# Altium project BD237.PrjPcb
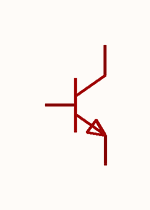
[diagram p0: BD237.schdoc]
1 sheet, 1 parts. Net scope: global (net labels, ports and power ports of the same name join across sheets).

## Sheet BD237.schdoc
size 127 x 101 mm

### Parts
Q?  bd237_c45991  [TO-126-3_L7.6-W2.7-P2.30-L]  (value not drawn)

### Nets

Not connected (* = marked no-connect by the designer): Q? 1(E) 2(C) 3(B)

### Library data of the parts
Q? = bd237_c45991: 晶体管类型:NPN;集电极电流(Ic):2A;集射极击穿电压(Vceo):80V;耗散功率(Pd):25W;直流电流增益(hFE):25;; Manufacturer: CJ(江苏长电/长晶); Symbol: BD237; AddInBom: yes; ModelId: 7e16fa0fc5b945c899301d14551435f6; ModelTransform: 299.212,106.6927,0,0,0,0,0,7.992,-196.85; type: NPN; Current - Collector(Ic): 2A; Collector - Emitter Voltage VCEO: 80V; Pd - Power Dissipation: 25W; DC Current Gain: 25; Transition frequency(fT): 3MHz; Current - Collector Cutoff: 100uA; Vce Saturation(VCE(sat)): 600mV; Emitter-Base Voltage(Vebo): 5V; Number: 1个NPN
